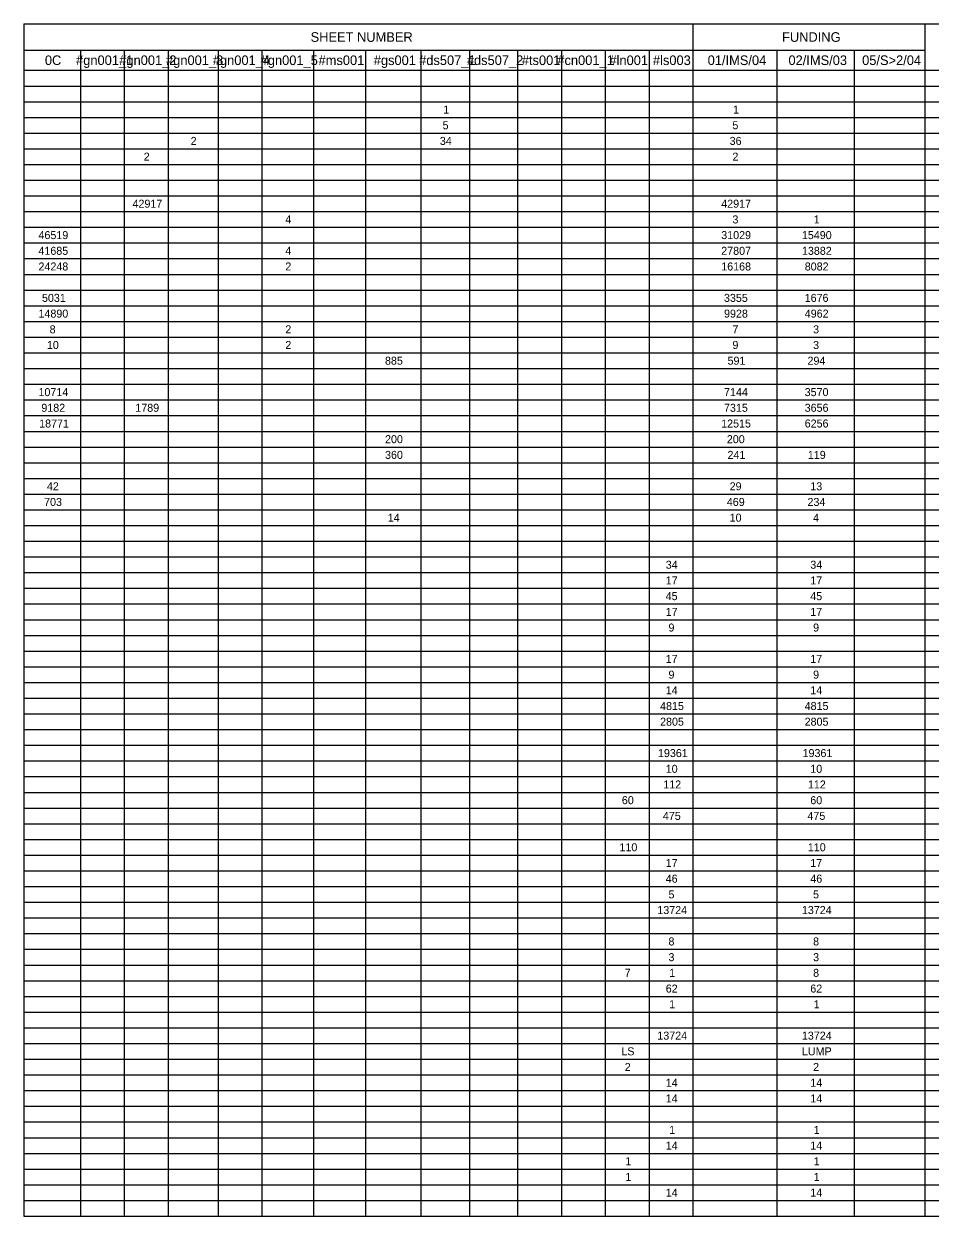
# Model space of a CAD drawing. Extents: x -542 to 295, y -281 to 32.
# Drawn here: x -541.71 to -525.86, y -70.44 to -49.59 of the extents above; entities that cross this region are included whole.
import ezdxf

# ---------------------------------------------------------------- set-up
doc = ezdxf.new("R2010")
doc.units = 0
doc.layers.add('SH_Data', color=7, linetype='Continuous')
doc.layers.add('SH_Text', color=7, linetype='Continuous')

msp = doc.modelspace()

# ---------------------------------------------------------------- linework, layer by layer
at = {"layer": 'SH_Data'}
for p, q in [((-541.706, -49.593), (-511.206, -49.593)), ((-541.706, -49.593), (-541.706, -50.68)), ((-530.01, -49.593), (-530.01, -70.444)), ((-525.956, -49.593), (-525.956, -70.444)), ((-541.706, -50.054), (-525.956, -50.054)), ((-540.716, -50.054), (-540.716, -70.444)), ((-539.95, -50.054), (-539.95, -70.444)), ((-539.184, -50.054), (-539.184, -70.444)), ((-538.311, -50.054), (-538.311, -70.444)), ((-537.545, -50.054), (-537.545, -70.444)), ((-536.64, -50.054), (-536.64, -70.444)), ((-535.736, -50.054), (-535.736, -70.444)), ((-534.767, -50.054), (-534.767, -70.444)), ((-533.916, -50.054), (-533.916, -70.444)), ((-533.075, -50.054), (-533.075, -70.444)), ((-532.309, -50.054), (-532.309, -70.444)), ((-531.543, -50.054), (-531.543, -70.444)), ((-530.776, -50.054), (-530.776, -70.444)), ((-528.542, -50.054), (-528.542, -70.444)), ((-527.19, -50.054), (-527.19, -70.444)), ((-541.706, -50.405), (-511.206, -50.405)), ((-541.706, -50.68), (-511.206, -50.68)), ((-541.706, -50.68), (-541.706, -50.954)), ((-541.706, -50.954), (-511.206, -50.954)), ((-541.706, -50.954), (-541.706, -70.444)), ((-541.706, -51.229), (-511.206, -51.229)), ((-541.706, -51.503), (-511.206, -51.503)), ((-541.706, -51.778), (-511.206, -51.778)), ((-541.706, -52.052), (-511.206, -52.052)), ((-541.706, -52.327), (-511.206, -52.327)), ((-541.706, -52.601), (-511.206, -52.601)), ((-541.706, -52.876), (-511.206, -52.876)), ((-541.706, -53.15), (-511.206, -53.15)), ((-541.706, -53.425), (-511.206, -53.425)), ((-541.706, -53.699), (-511.206, -53.699)), ((-541.706, -53.974), (-511.206, -53.974)), ((-541.706, -54.248), (-511.206, -54.248)), ((-541.706, -54.523), (-511.206, -54.523)), ((-541.706, -54.797), (-511.206, -54.797)), ((-541.706, -55.072), (-511.206, -55.072)), ((-541.706, -55.346), (-511.206, -55.346)), ((-541.706, -55.621), (-511.206, -55.621)), ((-541.706, -55.895), (-511.206, -55.895)), ((-541.706, -56.17), (-511.206, -56.17)), ((-541.706, -56.444), (-511.206, -56.444)), ((-541.706, -56.719), (-511.206, -56.719)), ((-541.706, -56.993), (-511.206, -56.993)), ((-541.706, -57.268), (-511.206, -57.268)), ((-541.706, -57.542), (-511.206, -57.542)), ((-541.706, -57.817), (-511.206, -57.817)), ((-541.706, -58.091), (-511.206, -58.091)), ((-541.706, -58.366), (-511.206, -58.366)), ((-541.706, -58.64), (-511.206, -58.64)), ((-541.706, -58.915), (-511.206, -58.915)), ((-541.706, -59.189), (-511.206, -59.189)), ((-541.706, -59.464), (-511.206, -59.464)), ((-541.706, -59.738), (-511.206, -59.738)), ((-541.706, -60.013), (-511.206, -60.013)), ((-541.706, -60.287), (-511.206, -60.287)), ((-541.706, -60.562), (-511.206, -60.562)), ((-541.706, -60.836), (-511.206, -60.836)), ((-541.706, -61.111), (-511.206, -61.111)), ((-541.706, -61.385), (-511.206, -61.385)), ((-541.706, -61.66), (-511.206, -61.66)), ((-541.706, -61.935), (-511.206, -61.935)), ((-541.706, -62.209), (-511.206, -62.209)), ((-541.706, -62.484), (-511.206, -62.484)), ((-541.706, -62.758), (-511.206, -62.758)), ((-541.706, -63.033), (-511.206, -63.033)), ((-541.706, -63.307), (-511.206, -63.307)), ((-541.706, -63.582), (-511.206, -63.582)), ((-541.706, -63.856), (-511.206, -63.856)), ((-541.706, -64.131), (-511.206, -64.131)), ((-541.706, -64.405), (-511.206, -64.405)), ((-541.706, -64.68), (-511.206, -64.68)), ((-541.706, -64.954), (-511.206, -64.954)), ((-541.706, -65.229), (-511.206, -65.229)), ((-541.706, -65.503), (-511.206, -65.503)), ((-541.706, -65.778), (-511.206, -65.778)), ((-541.706, -66.052), (-511.206, -66.052)), ((-541.706, -66.327), (-511.206, -66.327)), ((-541.706, -66.601), (-511.206, -66.601)), ((-541.706, -66.876), (-511.206, -66.876)), ((-541.706, -67.15), (-511.206, -67.15)), ((-541.706, -67.425), (-511.206, -67.425)), ((-541.706, -67.699), (-511.206, -67.699)), ((-541.706, -67.974), (-511.206, -67.974)), ((-541.706, -68.248), (-511.206, -68.248)), ((-541.706, -68.523), (-511.206, -68.523)), ((-541.706, -68.797), (-511.206, -68.797)), ((-541.706, -69.072), (-511.206, -69.072)), ((-541.706, -69.346), (-511.206, -69.346)), ((-541.706, -69.621), (-511.206, -69.621)), ((-541.706, -69.895), (-511.206, -69.895)), ((-541.706, -70.17), (-511.206, -70.17)), ((-541.706, -70.444), (-511.206, -70.444))]:
    msp.add_line(p, q, dxfattribs=at)

# ---------------------------------------------------------------- texts
at = {"layer": 'SH_Text'}
for s, height, p in [('SHEET NUMBER', 0.168, (-536.693, -49.907)), ('FUNDING', 0.168, (-528.452, -49.907)), ('0C', 0.168, (-541.338, -50.313)), ('#gn001_1', 0.168, (-540.793, -50.313)), ('#gn001_2', 0.168, (-540.038, -50.313)), ('#gn001_3', 0.168, (-539.22, -50.313)), ('#gn001_4', 0.168, (-538.402, -50.313)), ('#gn001_5', 0.168, (-537.566, -50.313)), ('#ms001', 0.168, (-536.554, -50.313)), ('#gs001', 0.168, (-535.589, -50.313)), ('#ds507_1', 0.168, (-534.796, -50.313)), ('#ds507_2', 0.168, (-533.962, -50.313)), ('#ts001', 0.168, (-533.001, -50.313)), ('#cn001_1', 0.168, (-532.38, -50.313)), ('#ln001', 0.168, (-531.469, -50.313)), ('#ls003', 0.168, (-530.709, -50.313)), ('01/IMS/04', 0.168, (-529.752, -50.313)), ('02/IMS/03', 0.168, (-528.34, -50.313)), ('05/S>2/04', 0.168, (-527.052, -50.313)), ('1', 0.14, (-534.373, -51.161)), ('1', 0.14, (-529.308, -51.161)), ('5', 0.14, (-534.385, -51.436)), ('5', 0.14, (-529.32, -51.436)), ('2', 0.14, (-538.79, -51.71)), ('34', 0.14, (-534.434, -51.71)), ('36', 0.14, (-529.368, -51.71)), ('2', 0.14, (-539.61, -51.985)), ('2', 0.14, (-529.319, -51.985)), ('42917', 0.14, (-539.806, -52.808)), ('42917', 0.14, (-529.515, -52.808)), ('4', 0.14, (-537.136, -53.083)), ('3', 0.14, (-529.319, -53.083)), ('1', 0.14, (-527.898, -53.083)), ('46519', 0.14, (-541.45, -53.357)), ('31029', 0.14, (-529.515, -53.357)), ('15490', 0.14, (-528.105, -53.357)), ('41685', 0.14, (-541.451, -53.632)), ('4', 0.14, (-537.136, -53.632)), ('27807', 0.14, (-529.515, -53.632)), ('13882', 0.14, (-528.104, -53.632)), ('24248', 0.14, (-541.45, -53.906)), ('2', 0.14, (-537.135, -53.906)), ('16168', 0.14, (-529.515, -53.906)), ('8082', 0.14, (-528.055, -53.906)), ('5031', 0.14, (-541.389, -54.455)), ('3355', 0.14, (-529.467, -54.455)), ('1676', 0.14, (-528.056, -54.455)), ('14890', 0.14, (-541.45, -54.73)), ('9928', 0.14, (-529.466, -54.73)), ('4962', 0.14, (-528.055, -54.73)), ('8', 0.14, (-541.255, -55.005)), ('2', 0.14, (-537.135, -55.005)), ('7', 0.14, (-529.319, -55.005)), ('3', 0.14, (-527.909, -55.005)), ('10', 0.14, (-541.303, -55.279)), ('2', 0.14, (-537.135, -55.279)), ('9', 0.14, (-529.319, -55.279)), ('3', 0.14, (-527.909, -55.279)), ('885', 0.14, (-535.393, -55.554)), ('591', 0.14, (-529.405, -55.554)), ('294', 0.14, (-528.007, -55.554)), ('10714', 0.14, (-541.45, -56.103)), ('7144', 0.14, (-529.466, -56.103)), ('3570', 0.14, (-528.056, -56.103)), ('9182', 0.14, (-541.4, -56.377)), ('1789', 0.14, (-539.757, -56.377)), ('7315', 0.14, (-529.467, -56.377)), ('3656', 0.14, (-528.056, -56.377)), ('18771', 0.14, (-541.438, -56.652)), ('12515', 0.14, (-529.516, -56.652)), ('6256', 0.14, (-528.056, -56.652)), ('200', 0.14, (-535.392, -56.926)), ('200', 0.14, (-529.417, -56.926)), ('360', 0.14, (-535.392, -57.201)), ('241', 0.14, (-529.405, -57.201)), ('119', 0.14, (-528.001, -57.201)), ('42', 0.14, (-541.303, -57.75)), ('29', 0.14, (-529.368, -57.75)), ('13', 0.14, (-527.958, -57.75)), ('703', 0.14, (-541.352, -58.024)), ('469', 0.14, (-529.417, -58.024)), ('234', 0.14, (-528.007, -58.024)), ('14', 0.14, (-535.344, -58.299)), ('10', 0.14, (-529.368, -58.299)), ('4', 0.14, (-527.909, -58.299)), ('34', 0.14, (-530.485, -59.122)), ('34', 0.14, (-527.958, -59.122)), ('17', 0.14, (-530.486, -59.397)), ('17', 0.14, (-527.958, -59.397)), ('45', 0.14, (-530.486, -59.671)), ('45', 0.14, (-527.959, -59.671)), ('17', 0.14, (-530.486, -59.946)), ('17', 0.14, (-527.958, -59.946)), ('9', 0.14, (-530.437, -60.22)), ('9', 0.14, (-527.909, -60.22)), ('17', 0.14, (-530.486, -60.769)), ('17', 0.14, (-527.958, -60.769)), ('9', 0.14, (-530.437, -61.044)), ('9', 0.14, (-527.909, -61.044)), ('14', 0.14, (-530.485, -61.318)), ('14', 0.14, (-527.958, -61.318)), ('4815', 0.14, (-530.584, -61.593)), ('4815', 0.14, (-528.057, -61.593)), ('2805', 0.14, (-530.584, -61.867)), ('2805', 0.14, (-528.057, -61.867)), ('19361', 0.14, (-530.621, -62.416)), ('19361', 0.14, (-528.093, -62.416)), ('10', 0.14, (-530.485, -62.691)), ('10', 0.14, (-527.958, -62.691)), ('112', 0.14, (-530.528, -62.965)), ('112', 0.14, (-528, -62.965)), ('60', 0.14, (-531.252, -63.24)), ('60', 0.14, (-527.958, -63.24)), ('475', 0.14, (-530.535, -63.514)), ('475', 0.14, (-528.008, -63.514)), ('110', 0.14, (-531.294, -64.063)), ('110', 0.14, (-528.001, -64.063)), ('17', 0.14, (-530.486, -64.338)), ('17', 0.14, (-527.958, -64.338)), ('46', 0.14, (-530.486, -64.612)), ('46', 0.14, (-527.958, -64.612)), ('5', 0.14, (-530.437, -64.887)), ('5', 0.14, (-527.91, -64.887)), ('13724', 0.14, (-530.632, -65.161)), ('13724', 0.14, (-528.105, -65.161)), ('8', 0.14, (-530.437, -65.71)), ('8', 0.14, (-527.909, -65.71)), ('3', 0.14, (-530.437, -65.985)), ('3', 0.14, (-527.909, -65.985)), ('7', 0.14, (-531.203, -66.259)), ('1', 0.14, (-530.425, -66.259)), ('8', 0.14, (-527.909, -66.259)), ('62', 0.14, (-530.485, -66.534)), ('62', 0.14, (-527.958, -66.534)), ('1', 0.14, (-530.425, -66.808)), ('1', 0.14, (-527.898, -66.808)), ('13724', 0.14, (-530.632, -67.357)), ('13724', 0.14, (-528.105, -67.357)), ('LS', 0.14, (-531.261, -67.632)), ('LUMP', 0.14, (-528.104, -67.632)), ('2', 0.14, (-531.202, -67.906)), ('2', 0.14, (-527.909, -67.906)), ('14', 0.14, (-530.485, -68.181)), ('14', 0.14, (-527.958, -68.181)), ('14', 0.14, (-530.485, -68.456)), ('14', 0.14, (-527.958, -68.456)), ('1', 0.14, (-530.425, -69.005)), ('1', 0.14, (-527.898, -69.005)), ('14', 0.14, (-530.485, -69.279)), ('14', 0.14, (-527.958, -69.279)), ('1', 0.14, (-531.191, -69.554)), ('1', 0.14, (-527.898, -69.554)), ('1', 0.14, (-531.191, -69.828)), ('1', 0.14, (-527.898, -69.828)), ('14', 0.14, (-530.485, -70.103)), ('14', 0.14, (-527.958, -70.103))]:
    msp.add_text(s, height=height, dxfattribs=at).set_placement(p)

doc.saveas('drawing.dxf')
